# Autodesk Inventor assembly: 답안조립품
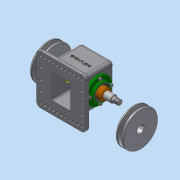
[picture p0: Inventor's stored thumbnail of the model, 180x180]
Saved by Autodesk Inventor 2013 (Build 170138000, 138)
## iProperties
Created: 2018-11
Part Number: 답안조립품
Document SubType Name: Assembly
Designer: dgall
Author: dgall
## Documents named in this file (10)
- C:\Users\dgall\Desktop\481107V1009\답안조립품.iam
- C:\Users\dgall\Desktop\481107V1009\본체.ipt
- C:\Users\dgall\Desktop\481107V1009\베어링 6203.ipt
- C:\Users\dgall\Desktop\481107V1009\축.ipt
- C:\Users\dgall\Desktop\481107V1009\부시.ipt
- C:\Users\dgall\Desktop\481107V1009\오일 실 26 38 8.ipt
- C:\Users\dgall\Desktop\481107V1009\커버.ipt
- C:\Users\dgall\Desktop\481107V1009\볼트 M4.ipt
- C:\Users\dgall\Desktop\481107V1009\키 5x5x12.ipt
- C:\Users\dgall\Desktop\481107V1009\V벨트풀리.ipt
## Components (2 placed, 1 different names)
1. V벨트풀리:1
2. V벨트풀리:2
